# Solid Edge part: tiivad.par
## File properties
Author: Georg
Template: Iso Metric Part.par
Last saved by: Georg
Revision: 7
Application: Solid Edge
Accuracy: 0,990
Face Style: Model Default
Fill Style: Normal
Coef. of Thermal Exp: 0.0
Thermal Conductivity: 0.0
Specific Heat: 0.0
Modulus of Elasticity: 0.0
Poisson's Ratio: 0.0
Yield Stress: 0.0
Ultimate Stress: 0.0
Elongation: 0.0
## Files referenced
!C:\Users\Georg\Desktop\lennuk.asm
..\lennuk.asm
C:\Users\Georg\Desktop\kere.par
C:\Users\Georg\Desktop\tiivad.par
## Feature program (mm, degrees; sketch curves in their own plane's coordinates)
lofted protrusion "unnamed LoftedProtrusion 1"
mirror "unnamed Mirror 1" of "unnamed LoftedProtrusion 1" about plane through (0, 1634.5531, -219.5298) normal (-1, 0, 0)
lofted protrusion "unnamed LoftedProtrusion 2"
sketch for "ExtrudedCutout_1" plane through (0, 0, 0) normal (0, 0, 1) x-axis (1, 0, 0)
extrude "ExtrudedCutout_1" cut finite 1329.1042 along -normal
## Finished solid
Body 1: solid body, 7 faces, 16 edges, 11 vertices.
  Faces by surface: spline 4, plane 2, swept 1
  Edges by curve: line 5, intersection 4, spline 4, ellipse 3
Bounding box of the edges (mm; curved faces can reach further): 8000.000 x 1753.844 x 345.264, from (-4000, 1134.2156, -388.2089) to (4000, 2888.0592, -42.9446).
Planar faces by outward normal: +x 1, -x 1
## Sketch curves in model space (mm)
line (4000, 2888.0592, -183.4407) -> (4000, 2888.0592, -182.031)
ellipse centre (4000, 2884.5531, -182.031) radii 3.5061, 0.903 from (4000, 2888.0592, -182.031) through (4000, 2884.4493, -181.1284) to (4000, 2881.0471, -182.031)
line (4000, 2881.0471, -182.031) -> (4000, 2888.0592, -183.4407)
line (2000, 1884.5531, -294.531) -> (2000, 1884.5531, -182.031)
ellipse centre (2000, 1634.5531, -182.031) radii 250, 75 from (2000, 1884.5531, -182.031) through (2000, 1627.1448, -107.064) to (2000, 1384.5531, -182.031)
line (2000, 1384.5531, -182.031) -> (2000, 1884.5531, -294.531)
line (0, 2134.5531, -407.031) -> (0, 2134.5531, -182.031)
ellipse centre (0, 1634.5531, -182.031) radii 500, 150 from (0, 2134.5531, -182.031) through (0, 1619.7365, -32.0969) to (0, 1134.5531, -182.031)
line (0, 1134.5531, -182.031) -> (0, 2134.5531, -407.031)
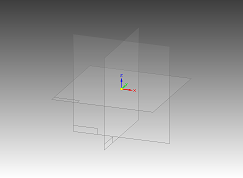
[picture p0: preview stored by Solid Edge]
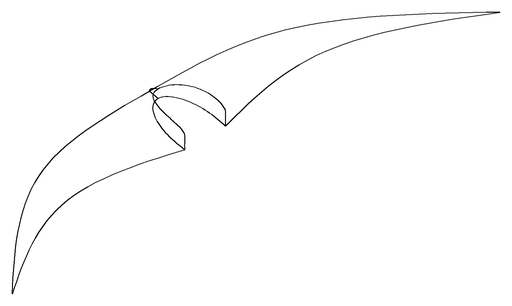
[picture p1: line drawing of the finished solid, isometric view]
